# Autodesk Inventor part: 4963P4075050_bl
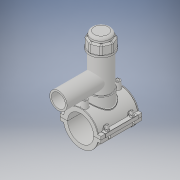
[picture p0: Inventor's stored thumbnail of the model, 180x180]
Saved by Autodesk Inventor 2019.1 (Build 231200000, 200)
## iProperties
Created: 2017-07
Part Number: 4963P4075050_bl
Material: Generic
Document SubType Name: Modeling
Designer: KIM
Density: 1 g/cm^3
Appearance: Default
Author: KIM
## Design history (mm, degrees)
derived "4963P4.ipt"
feature "Solid1::4963P4.ipt" dims "ScaleForDerivedMember" = 10
feature "Solid2::4963P4.ipt" dims "ScaleForDerivedMember" = 10
feature "Solid3::4963P4.ipt" dims "ScaleForDerivedMember" = 10
tag "TaggingFeature1"
body "Solid1"
body "Solid2"
body "Solid3"
other parameters: "d0" = 75 [user parameter], "d2" = 117 [user parameter], "d3" = 18.75 [user parameter], "d4" = 118 [user parameter], "d5" = 0 [user parameter], "d6" = 0.1 [user parameter], "d8" = 0 [user parameter], "d19" = 6 [user parameter], "d20" = 6 [user parameter], "d21" = 70.8 [user parameter], "d23" = 0 [user parameter], "d24" = 35.4 [user parameter], "d26" = 0 [user parameter], "d27" = 3 [user parameter], "d28" = 3 [user parameter], "d29" = 3 [user parameter], "d30" = 25 [user parameter], "d31" = 6 [user parameter], "d32" = 0 [user parameter], "d33" = 0 [user parameter], "d34" = 0.6 [user parameter], "d40" = 50.7 [user parameter], "d41" = 67.5 [user parameter], "d43" = 0 [user parameter], "d45" = 0 [user parameter], "d47" = 119.55 [user parameter], "d70" = 15 [user parameter], "d72" = 0 [user parameter], "d73" = 6 [user parameter], "d75" = 5 [user parameter], "d76" = 0 [user parameter], "d77" = 3.75 [user parameter], "d78" = 67.5 [user parameter], "d79" = 15 [user parameter], "d80" = 47.2 [user parameter], "d82" = 5 deg [user parameter], "d84" = 4 [user parameter], "d85" = 14 [user parameter], "d86" = 0 [user parameter], "d87" = 3 [user parameter], "d88" = 0 [user parameter], "d89" = 1 [user parameter], "d90" = 1 [user parameter], "d91" = 94.4 [user parameter], "d92" = 0 [user parameter], "d93" = 0.5 [user parameter], "d94" = 39.47368 [user parameter], "d96" = 99.45 [user parameter], "d97" = 2.36 [user parameter], "d98" = 0 [user parameter], "d102" = 0.75 [user parameter], "d120" = 140 deg [user parameter], "d121" = 24.228 [user parameter], "d122" = 20 deg [user parameter], "d123" = 195 [user parameter], "d124" = 58.5 [user parameter], "d126" = 0 [user parameter], "d143" = 77.25 [user parameter], "d145" = 17.30769 [user parameter], "d149" = 1.125 [user parameter], "d150" = 19.03846 [user parameter], "d153" = 118 [user parameter], "d154" = 0 [user parameter], "d156" = 48.75 [user parameter], "d157" = 160 deg [user parameter], "d159" = 4.5 [user parameter], "d161" = 1.125 [user parameter], "d162" = 70.8 [user parameter], "d163" = 0 [user parameter], "d164" = 37.5 [user parameter], "d167" = 7.5 [user parameter], "d168" = 47.56098 [user parameter], "d170" = 3.75 [user parameter], "d172" = 0 [user parameter], "d173" = 1 [user parameter], "d175" = 37.5 [user parameter], "d176" = 20 deg [user parameter], "d177" = 5.25 [user parameter], "d178" = 22.5 [user parameter], "d180" = 0 [user parameter], "d183" = 9 [user parameter], "d184" = 4.2 [user parameter], "d185" = 38.35 [user parameter], "d186" = 38.35 [user parameter], "d187" = 48.75 [user parameter], "d188" = 6.75 [user parameter], "d189" = 5.25 [user parameter], "d190" = 0 [user parameter], "d191" = 73.125 [user parameter], "d193" = 8 [user parameter], "d194" = 4.13 [user parameter], "d195" = 90 deg [user parameter], "d197" = 0 [user parameter], "d199" = 0 [user parameter], "d200" = 11.25 [user parameter], "d202" = 0 [user parameter], "d203" = 177 [user parameter], "d204" = 64.125 [user parameter], "d205" = 47.25 [user parameter], "d206" = 57.375 [user parameter], "d207" = 132.75 [user parameter], "d208" = 138.06 [user parameter], "d209" = 164.61 [user parameter], "d210" = 58.05 [user parameter], "d211" = 67.5 [user parameter], "d212" = 54 [user parameter], "d213" = 35.1 [user parameter], "d216" = 0 [user parameter], "d217" = 7.5 [user parameter], "d218" = 7.5 [user parameter], "d219" = 1.5 [user parameter], "d222" = 75 [user parameter], "d224" = 0 [user parameter], "d225" = 64 [user parameter], "d228" = 123 [user parameter], "d230" = 4.5 [user parameter], "d_" = 75 [user parameter], "B_" = 117 [user parameter], "L_" = 118 [user parameter], "d_t" = 6 [user parameter]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
